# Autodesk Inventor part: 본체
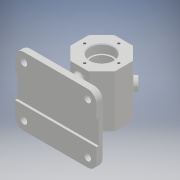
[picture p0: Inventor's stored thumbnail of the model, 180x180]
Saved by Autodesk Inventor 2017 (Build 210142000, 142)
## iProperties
Part Number: 본체
Material: 일반
Document SubType Name: Modeling
Designer: MRC
Density: 1 g/cm^3
Appearance: 기본값
Author: MRC
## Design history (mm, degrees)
sketch "스케치1"
  geometry: L1 (12.426, 30)-(30, 12.426); L2 (30, 12.426)-(30, -12.426); L3 (30, -12.426)-(12.426, -30); L4 (12.426, -30)-(-12.426, -30); L5 (-12.426, -30)-(-30, -12.426); L6 (-30, -12.426)-(-30, 12.426); L7 (-30, 12.426)-(-12.426, 30); L8 (-12.426, 30)-(12.426, 30); 2 further points
  constraints: 16 end point, 1 coincident, 1 horizontal, 17 other
  dimensions: "d0" = 30 distance from line of point (0, 0) L8
extrude "돌출1" new body sketch "스케치1" stored distance "d1" = 70; taper "d2" = 0 deg
hole "구멍1" diameter "d5" = 28; stored, may be unused: countersink angle "d9" = 90 deg, drill point angle "d11" = 0 deg; dims "d3" = 30, "d6" = 6, "d7" = 32, "d8" = 12, "d10" = 15, "d84" = 30
hole "구멍2" diameter "d15" = 50; stored, may be unused: countersink angle "d19" = 90 deg, drill point angle "d21" = 0 deg; dims "d12" = 10, "d13" = 10, "d16" = 6, "d17" = 4, "d18" = 2, "d20" = 40
sketch "스케치2"
  geometry: 2 further points
  constraints: 1 vertical alignment
  dimensions: "d22" = 23 distance of point (0, 0) point (0, 23)
hole "구멍3" sketch "스케치2" at (0, 23) diameter "d23" = 3.242; stored, may be unused: countersink angle "d27" = 90 deg, drill point angle "d29" = 118 deg; dims "d24" = 8, "d25" = 4, "d26" = 2, "d28" = 10
node "작업 평면3"
sketch "스케치3"
  geometry: L1 (0, 0)-(24.749, 24.749); L2 (0, 0)-(42.557, 0)
  constraints: 4 end point, 1 horizontal
  dimensions: "d34" = 35 distance of L1.start L1.end; "d35" = 45 deg angle of L2 L1
node "작업 평면4"
sketch "스케치4"
  geometry: C1 r 8 at (0, 0); 1 further point
  constraints: 1 centre point, 1 coincident
  dimensions: "d36" = 16 diameter of C1
extrude "돌출2" join sketch "스케치4" stored distance "d37" = 70; taper "d38" = 0 deg
hole "구멍4" diameter "d41" = 8; stored, may be unused: countersink angle "d45" = 90 deg, drill point angle "d47" = 118 deg; dims "d39" = 10, "d40" = 10, "d42" = 8, "d43" = 4, "d44" = 2, "d46" = 15.25
node "작업 평면5"
sketch "스케치5"
  geometry: L1 (55, -46)-(-55, -46); L2 (-55, -46)-(-55, 46); L3 (-55, 46)-(55, 46); L4 (55, 46)-(55, -46); L5 (55, -46)-(-55, 46); L6 (-55, -46)-(55, 46); 1 further point
  constraints: 12 end point, 2 midpoint, 2 parallel, 1 horizontal, 1 perpendicular
  dimensions: "d49" = 110 distance of L2.end L3.end; "d50" = 92 distance of L1.end L2.end
extrude "돌출3" join sketch "스케치5" distance "d51" = 10; taper "d52" = 0 deg
sketch "스케치6"
  geometry: L1 (0, 20)-(0, -20); L2 (-6, 20)-(-6, -20); L3 (6, -20)-(6, 20); A1 r 6 centre (0, 20) between (6, 20) and (-6, 20); A2 r 6 centre (0, -20) between (-6, -20) and (6, -20); 1 further point
  constraints: 8 end point, 4 point on circle, 4 tangent, 2 centre point, 1 midpoint, 1 parallel, 1 vertical
  dimensions: "d53" = 20 distance of point (0, 0) L1.end; "d54" = 12 diameter of A2
extrude "돌출4" join sketch "스케치6" stored distance "d55" = 10; taper "d56" = 0 deg
fillet "모깎기1" dims "d57" = 12
sketch "스케치7"
  geometry: L1 (-55, -34)-(-55, 34) reference; L2 (-43, 46)-(43, 46) reference; L3 (55, 34)-(55, -34) reference; L4 (43, -46)-(-43, -46) reference; A1 r 12 centre (-43, -34) between (-55, -34) and (-43, -46) reference; A2 r 12 centre (-43, 34) between (-43, 46) and (-55, 34) reference; A3 r 12 centre (43, 34) between (55, 34) and (43, 46) reference; A4 r 12 centre (43, -34) between (43, -46) and (55, -34) reference; 5 further points
  constraints: 4 coincident
hole "구멍5" sketch "스케치7" at (-43, 34), (-43, -34), (43, -34), (43, 34) diameter "d58" = 9; stored, may be unused: countersink angle "d62" = 90 deg, drill point angle "d64" = 118 deg; dims "d59" = 8, "d60" = 4, "d61" = 2, "d63" = 15.25
sketch "스케치8"
  geometry: L1 (18, 3)-(50, 3); L2 (50, 3)-(50, 0); L3 (50, 0)-(18, 0); L4 (18, 0)-(18, 3); L5 (68, 10)-(68, 0) reference; L6 (0, 10)-(68, 10) reference; L7 (0, 0)-(0, 10) reference; L8 (68, 0)-(0, 0) reference; L9 (68, 0)-(0, 0) reference; 3 further points
  constraints: 8 end point, 4 midpoint, 2 parallel, 1 horizontal, 1 perpendicular, 1 vertical alignment
  dimensions: "d65" = 32 distance of L2.end L3.end; "d66" = 3 distance of L1.end L2.end
extrude "돌출5" cut sketch "스케치8" stored distance "d67" = 10; taper "d68" = 0 deg
fillet "모깎기2" dims "d69" = 3
fillet "모깎기3" dims "d70" = 0.3
fillet "모깎기4" dims "d71" = 3
fillet "모깎기5" dims "d72" = 1
chamfer "모따기2" distance "d76" = 1; stored, may be unused: second distance "d77" = 2, angle "d78" = 45 deg
fillet "모깎기6" dims "d79" = 3
sketch "스케치9"
  geometry: 2 further points
  constraints: 1 coincident, 1 other
feature "엠보싱1" sketch "스케치9" dims "d0" = 30, "d80" = 0.5, "d81" = 0
fillet "모깎기7" dims "d82" = 1
node "솔리드1"
mirror "미러1"
pattern_circular "원형 패턴1" dims angle "d31" = 360 deg
mirror "미러2"
node "작업 평면1"
node "작업 평면2"
node "투영된 루프1"
node "투영된 루프2"
other parameters: "d33" = -35, "d48" = -62
